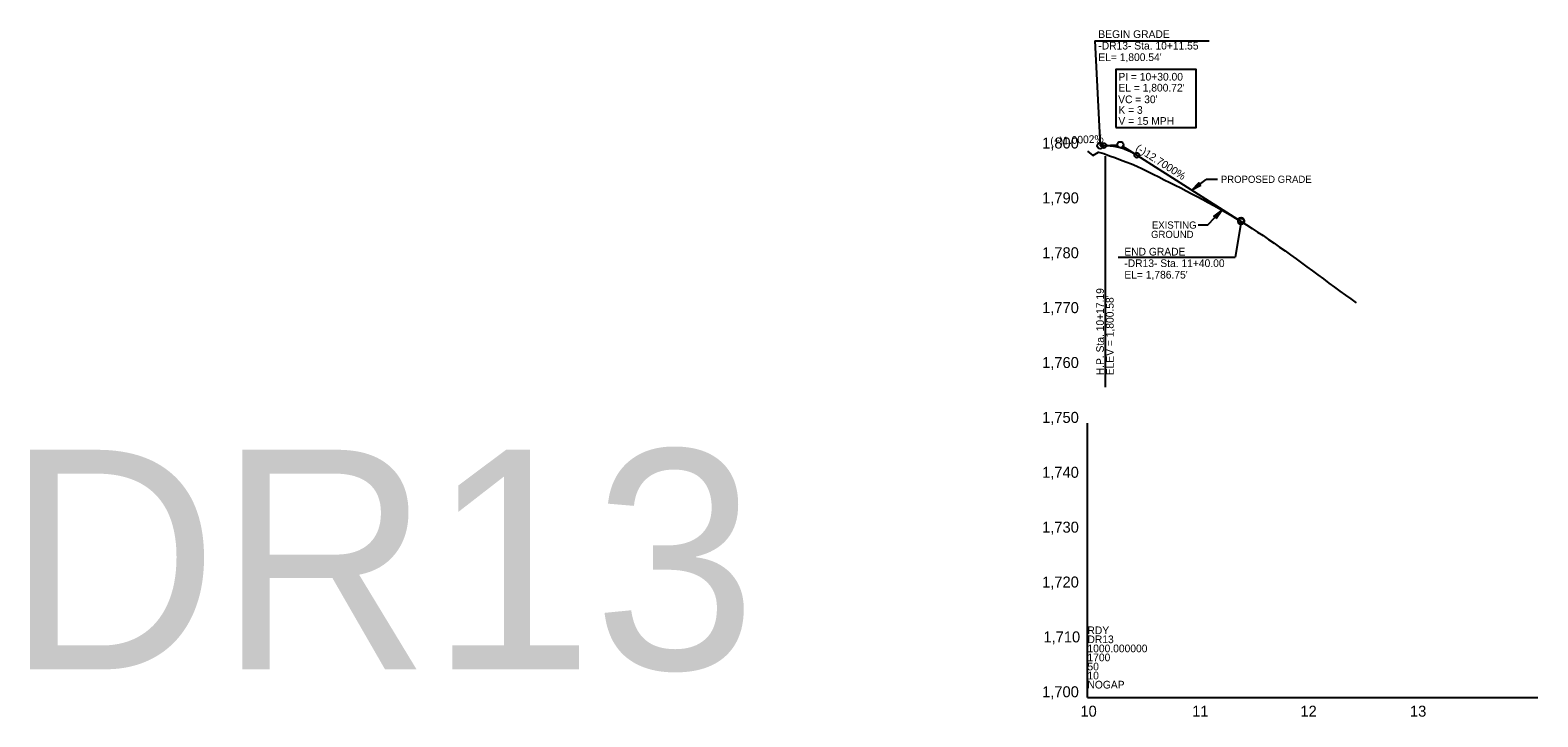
# Model space of a CAD drawing. Extents: x 498575 to 532350, y 405181 to 484585.
# Drawn here: x 526321 to 527694, y 453832 to 454457 of the extents above; entities that cross this region are included whole.
import ezdxf

# ---------------------------------------------------------------- set-up
doc = ezdxf.new("R2010")
doc.units = 0
for name, color, linetype in [('Exist Profile Cell', 7, 'Continuous'), ('Exist Vertical Profile Ground Line', 7, 'Continuous'), ('Exist Vertical Profile Horizontal Axis Label Major', 7, 'Continuous'), ('Exist Vertical Profile Vertical Axis Label', 7, 'Continuous'), ('Prop Grid Mask', 7, 'Continuous'), ('Prop PFL Text', 7, 'Continuous'), ('Prop Vertical Profile Curve Label', 7, 'Continuous'), ('Prop Vertical Profile Grade', 7, 'Continuous'), ('Prop Vertical Profile Grade Label', 7, 'Continuous'), ('Prop Vertical Profile Strip Grade', 7, 'Continuous'), ('Prop VPI Label', 7, 'Continuous'), ('Scratch_Level_7', 7, 'Continuous')]:
    doc.layers.add(name, color=color, linetype=linetype)

msp = doc.modelspace()

# ---------------------------------------------------------------- linework, layer by layer
at = {"layer": 'Exist Profile Cell'}
for q in [(527283.8, 454099.4), (527694.1, 453849.4), (527283.8, 453849.4)]:
    msp.add_line((527283.8, 453849.4), q, dxfattribs=at)
at = {"layer": 'Exist Vertical Profile Ground Line'}
msp.add_lwpolyline([(527283.8, 454347.3), (527288.8, 454343.3), (527293.8, 454346.2), (527298.8, 454345), (527303.8, 454343), (527308.8, 454341.3), (527313.8, 454339.4), (527318.8, 454337.5), (527323.8, 454335.5), (527328.8, 454333.6), (527333.8, 454331.1), (527338.8, 454328.6), (527343.8, 454326.2), (527348.8, 454323.7), (527353.8, 454321.2), (527358.8, 454318.7), (527363.8, 454316.2), (527368.8, 454313.7), (527373.8, 454311.1), (527378.8, 454308.4), (527383.8, 454305.8), (527388.8, 454303.1), (527393.8, 454300.4), (527398.8, 454297.7), (527403.8, 454294.9), (527408.8, 454292), (527413.8, 454289.1), (527418.8, 454286.2), (527423.8, 454283.2), (527428.8, 454280), (527433.8, 454276.8), (527438.8, 454273.5), (527443.8, 454270.2), (527448.8, 454266.8), (527453.8, 454263.3), (527458.8, 454259.8), (527463.8, 454256.3), (527468.8, 454252.6), (527473.8, 454249.1), (527478.8, 454245.5), (527483.8, 454241.9), (527488.8, 454238.2), (527493.8, 454234.5), (527498.8, 454230.8), (527503.8, 454227), (527508.8, 454223.3), (527513.8, 454219.7), (527518.8, 454216), (527523.8, 454212.5), (527528.7, 454209)], dxfattribs=at)
at = {"layer": 'Prop Grid Mask'}
msp.add_lwpolyline([(527309.8, 454368.6), (527382.8, 454368.6), (527382.8, 454421.7), (527309.8, 454421.7)], close=True, dxfattribs=at)
at = {"layer": 'Prop PFL Text'}
for p, q in [((527379, 454311.6), (527392, 454321.5)), ((527402.2, 454321.5), (527392, 454321.5)), ((527393.5, 454280.2), (527406.3, 454293.5)), ((527384.8, 454280.2), (527393.5, 454280.2))]:
    msp.add_line(p, q, dxfattribs=at)
for points in [[(527387.1, 454315.9), (527379, 454311.6), (527385.2, 454318.4), (527385.3, 454316.4)], [(527401.2, 454285.9), (527406.3, 454293.5), (527398.9, 454288.1), (527400.8, 454287.8)]]:
    msp.add_lwpolyline(points, close=True, dxfattribs=at)
at = {"layer": 'Prop Vertical Profile Curve Label'}
for centre in [(527298.8, 454352.3), (527328.8, 454343.5)]:
    msp.add_circle(centre, 2.25, dxfattribs=at)
at = {"layer": 'Prop Vertical Profile Grade'}
for p, q in [((527295.4, 454352.1), (527298.8, 454352.3)), ((527328.8, 454343.5), (527423.8, 454283.2))]:
    msp.add_line(p, q, dxfattribs=at)
msp.add_spline([(527298.8, 454352.3), (527299.4, 454352.3), (527300, 454352.3), (527300.6, 454352.3), (527301.2, 454352.3), (527301.8, 454352.3), (527302.4, 454352.3), (527303, 454352.3), (527303.6, 454352.2), (527304.2, 454352.2), (527304.8, 454352.1), (527305.4, 454352.1), (527306, 454352), (527306.6, 454352), (527307.2, 454351.9), (527307.8, 454351.8), (527308.4, 454351.7), (527309, 454351.6), (527309.6, 454351.5), (527310.2, 454351.3), (527310.8, 454351.2), (527311.4, 454351.1), (527312, 454350.9), (527312.6, 454350.8), (527313.2, 454350.6), (527313.8, 454350.4), (527314.4, 454350.3), (527315, 454350.1), (527315.6, 454349.9), (527316.2, 454349.7), (527316.8, 454349.5), (527317.4, 454349.2), (527318, 454349), (527318.6, 454348.8), (527319.2, 454348.5), (527319.8, 454348.3), (527320.4, 454348), (527321, 454347.7), (527321.6, 454347.5), (527322.2, 454347.2), (527322.8, 454346.9), (527323.4, 454346.6), (527324, 454346.3), (527324.6, 454346), (527325.2, 454345.6), (527325.8, 454345.3), (527326.4, 454344.9), (527327, 454344.6), (527327.6, 454344.2), (527328.2, 454343.9), (527328.8, 454343.5)], degree=3, dxfattribs=at)
at = {"layer": 'Prop Vertical Profile Strip Grade'}
msp.add_line((527299.8, 454342.7), (527299.8, 454132.2), dxfattribs=at)
at = {"layer": 'Prop VPI Label'}
for p, q in [((527290.6, 454447.8), (527394.8, 454447.8)), ((527290.6, 454447.8), (527295.4, 454352.1)), ((527298.8, 454352.3), (527311, 454352.9)), ((527328.8, 454343.5), (527316.1, 454351.5)), ((527423.8, 454283.2), (527418.4, 454250.5)), ((527311.9, 454250.5), (527418.4, 454250.5))]:
    msp.add_line(p, q, dxfattribs=at)
for centre in [(527295.4, 454352.1), (527313.8, 454353), (527423.8, 454284), (527423.8, 454283.2)]:
    msp.add_circle(centre, 2.75, dxfattribs=at)

# ---------------------------------------------------------------- texts
at = {"layer": 'Exist Profile Cell'}
for s, p in [('RDY', (527283.8, 453907.1)), ('DR13', (527283.8, 453898.9)), ('1000.000000', (527283.8, 453890.6)), ('1700', (527283.8, 453882.4)), ('50', (527283.8, 453874.1)), ('10', (527283.8, 453865.9)), ('NOGAP', (527283.8, 453857.6))]:
    msp.add_text(s, height=7, dxfattribs=at).set_placement(p)
at = {"layer": 'Exist Vertical Profile Horizontal Axis Label Major'}
for s, p in [('10', (527277.4, 453831.9)), ('11', (527379.2, 453831.9)), ('12', (527477.8, 453831.9)), ('13', (527577.6, 453831.9))]:
    msp.add_text(s, height=10, dxfattribs=at).set_placement(p)
at = {"layer": 'Exist Vertical Profile Vertical Axis Label'}
for s, p in [('1,800', (527242.5, 454349.6)), ('1,790', (527242.5, 454299.6)), ('1,780', (527242.5, 454249.6)), ('1,770', (527242.5, 454199.6)), ('1,760', (527242.5, 454149.6)), ('1,750', (527242.5, 454099.6)), ('1,740', (527242.5, 454049.6)), ('1,730', (527242.5, 453999.6)), ('1,720', (527242.5, 453949.6)), ('1,710', (527243.7, 453899.6)), ('1,700', (527242.5, 453849.6))]:
    msp.add_text(s, height=10, dxfattribs=at).set_placement(p)
at = {"layer": 'Prop PFL Text'}
for s, height, p in [('PROPOSED GRADE', 6.516, (527405.3, 454318.3)), ('GROUND', 6.52, (527341.7, 454268.1)), ('EXISTING ', 6.52, (527342.5, 454276.6))]:
    msp.add_text(s, height=height, dxfattribs=at).set_placement(p)
at = {"layer": 'Prop Vertical Profile Curve Label'}
msp.add_text('V = 15 MPH ', height=7, dxfattribs=at).set_placement((527312, 454371.2))
at = {"layer": 'Prop Vertical Profile Grade Label'}
for s, rotation, p in [('(+)1.0002%', 2.8631, (527250.1, 454352.8)), ('(-)12.7000%', 327.5845, (527327, 454348.2))]:
    msp.add_text(s, height=7, rotation=rotation, dxfattribs=at).set_placement(p)
at = {"layer": 'Prop Vertical Profile Strip Grade'}
for s, p in [('H.P. Sta. 10+17.19', (527298.8, 454143)), ("ELEV = 1,800.58'", (527307.7, 454143))]:
    msp.add_text(s, height=7, rotation=90, dxfattribs=at).set_placement(p)
at = {"layer": 'Prop VPI Label'}
for s, p in [('BEGIN GRADE', (527293.7, 454450.3)), ('-DR13- Sta. 10+11.55', (527293.7, 454439.8)), ("EL= 1,800.54'", (527293.7, 454429.3)), ('PI = 10+30.00', (527312, 454411.5)), ("VC = 30'", (527311.8, 454390.9)), ("EL = 1,800.72'", (527312, 454401.5)), ('K = 3', (527312, 454381.2)), ('END GRADE ', (527317.4, 454252.1)), ('-DR13- Sta. 11+40.00', (527317.4, 454241.6)), ("EL= 1,786.75'", (527317.4, 454231.1))]:
    msp.add_text(s, height=7, dxfattribs=at).set_placement(p)
at = {"layer": 'Scratch_Level_7'}
msp.add_text('DR13', height=200, dxfattribs=at).set_placement((526298.7, 453875.1))

doc.saveas('drawing.dxf')
